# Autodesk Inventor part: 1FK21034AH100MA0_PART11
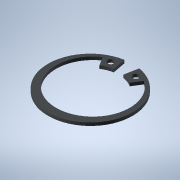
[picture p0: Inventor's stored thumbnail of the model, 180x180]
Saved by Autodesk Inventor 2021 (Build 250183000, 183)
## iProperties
Created: 2025-04
Part Number: 1FK21034AH100MA0_PART11
Material: Generic
Catalog Web Link: www.3dfindit.com
Description: -Servo synchronous motor
Document SubType Name: Modeling
Designer: psAdmin
Mass: 0.288797 g
Surface Area: 7.43416 cm^2
Volume: 0.288797 cm^3
Density: 1 g/cm^3
Appearance: PSOLRGB-212-217-219
Category: PARTsolutions
Title: 1FK21034AH100MA0_PART11
Author: Cadenas PARTsolutions
Comments: Servo synchronous motor
Sending System: PARTsolutions
Preprocessor: ST-DEVELOPER v19.3
PSOL_IDENT_0: {$CADENAS_DATA/23d-libs/siemens_ag/_cat_/39/97/1fk21034ah100ma0.prj},216 {VTYP=3D},{NB=1FK21034AH100
PSOL_IDENT_1: MA0_PART11},{LINA=1FK21034AH100MA0_PART11},{NN=1FK21034AH100MA0_PART11},{NOPRJ=TRUE},{DATE=19.08.202
PSOL_IDENT_2: 5 14:00:33},{GEOMDATE=30.07.2025 02:02:21},{VERSION=},{LINEID=10},{WBVAR=},{WBNUMERIC=}  {NB=1FK2103
PSOL_IDENT_3: 4AH100MA0_PART11},{LINA=1FK21034AH100MA0_PART11},{KT=DUMMY},{PREVIEW=../../../_pool_/d3/78/p_d211_xx
PSOL_IDENT_4: _00934j.png},{DESCSHORT=SIMOTICS S-1FK2 HD, SINAMICS S210 3AC 400V-480V, 1.01 Nm, 4500 rpm},{DESCLON
PSOL_IDENT_5: G=SIMOTICS S-1FK2 HD servo motor M0=1.27 Nm; PN = 0.48 kW at nN=4500 rpm (380-480 V); PN = 0.3 kW at
PSOL_IDENT_6: nN=2500 rpm (200-240 V); with holding brake; degree of protection IP64; cylindrical shaft D14 x 30
PSOL_IDENT_7: mm; absolute encoder 22-bit + 12-bit multiturn (encoder AM22DQC); with OCC interface; plug size M17,
PSOL_IDENT_8: rotatable; SIMOTICS S-1FK2 servomotorfor a wide range of uses in industrial environments. SIMOTICS
PSOL_IDENT_9: S‑1FK2 servomotors are compact synchronous motors with a high dynamic performance that set themselve
PSOL_IDENT_10: s apart as a result of their high power density, degree of protection and overload capability. The m
PSOL_IDENT_11: otors are available in two variants: as High Dynamic variant (highest dynamic performance as a resul
PSOL_IDENT_12: t of the low intrinsic moment of inertia for applications demanding a high dynamic performance with
PSOL_IDENT_13: low moved masses) - and as Compact variant (precise and stable closed-loop control for medium up to
PSOL_IDENT_14: large moved masses as a result of a medium intrinsic moment of inertia). SIMOTICSS‑1FK2 servomotors
PSOL_IDENT_15: fully exploit their strengths in a system with the SINAMICSS210 frequency converter and simple conne
PSOL_IDENT_16: ction using the one cable connection (OCC). Advantages include the short control and positioning tim
PSOL_IDENT_17: es, fast and precise correction of disturbing quantities as well as stable control with a high dynam
PSOL_IDENT_18: ic performance. The servo motors can be configured to address a wide range of requirements. For exam
PSOL_IDENT_19: ple with and without holding brake, IP64 or IP65 degree of protection, singleturn or multiturn absol
PSOL_IDENT_20: ute encoders - to name just a few. Further, the servomotors are available in different shaft heights
PSOL_IDENT_21: extending from 20 to 100. A shaft sealing ring is available to achieve an IP65 degree of protection
PSOL_IDENT_22: and for subsequent mounting at the motor or as spare part. SIMOTICS - the optimum motor for each an
PSOL_IDENT_23: d every motion control application.},{INTNO=195125454019},{SUPPLIERALTNO=1FK2103-4AH10-0MA0},{MANUID=
PSOL_IDENT_24: 1FK21034AH100MA0},{MANUNAME=Siemens},{MANUTYPEDESC=SYNCHRONOUS MOTOR 1FK2 HD 1,27 NM},{AAU732=SIMOTI
PSOL_IDENT_25: CS},{AAO057=S-1FK2},{AAU734=SIMOTICS S-1FK2 HD servo motor M0=1.27 Nm; PN = 0.48 kW at nN=4500 rpm (
PSOL_IDENT_26: 380-480 V); PN = 0.3 kW at nN=2500 rpm (200-240 V); with holding brake; degree of protection IP64; c
PSOL_IDENT_27: ylindrical shaft D14 x 30 mm; absolute encoder 22-bit + 12-bit multiturn (encoder AM22DQC); with OCC
PSOL_IDENT_28: interface; plug size M17, rotatable;},{AAW338=SYNCHRONOUS MOTOR 1FK2 HD 1,27 NM},{AAO742=SIMOTICS},
PSOL_IDENT_29: {AAO663=4034106444921},{NOCUPEROU=1},{PRICEQUANTITY=1},{QUANTITYMIN=1},{QUANTITYINT=1},{CTN=85015100
PSOL_IDENT_30: },{COO=RO},{AAO676=1FK2103-4AH10-0MA0},{AAO677=Siemens AG},{ORDERUNIT=C62},{CONTENTUNIT=C62}
NB: 1FK21034AH100MA0_PART11
NT: Servo synchronous motor
NBSYN: $MANUID._PART11
LINA: 1FK21034AH100MA0_PART11
CATALOG: SIEMENS
PREVIEW: ../../../_pool_/d3/78/p_d211_xx_00934j.png
DESCSHORT: SIMOTICS S-1FK2 HD, SINAMICS S210 3AC 400V-480V, 1.01 Nm, 4500 rpm
DESCLONG: SIMOTICS S-1FK2 HD servo motor M0=1.27 Nm; PN = 0.48 kW at nN=4500 rpm (380-480 V); PN = 0.3 kW at nN=2500 rpm (200-240 V); with holding brake; degree of protec
INTNO: 195125454019
SUPPLIERALTNO: 1FK2103-4AH10-0MA0
MANUID: 1FK21034AH100MA0
MANUNAME: Siemens
MANUTYPEDESC: SYNCHRONOUS MOTOR 1FK2 HD 1,27 NM
AAU732: SIMOTICS
AAO057: S-1FK2
AAU734: SIMOTICS S-1FK2 HD servo motor M0=1.27 Nm; PN = 0.48 kW at nN=4500 rpm (380-480 V); PN = 0.3 kW at nN=2500 rpm (200-240 V); with holding brake; degree of protec
AAW338: SYNCHRONOUS MOTOR 1FK2 HD 1,27 NM
AAO742: SIMOTICS
AAO663: 4034106444921.0
NOCUPEROU: 1
PRICEQUANTITY: 1
QUANTITYMIN: 1
QUANTITYINT: 1
CTN: 85015100
COO: RO
ARTICLENO: 1FK21034AH100MA0_PART11
BOMINFO: 1FK21034AH100MA0_PART11
CREATOR: CADENAS GmbH
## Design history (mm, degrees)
feature "2025_04_17_15_09_00_0361"
body "Solid1"
